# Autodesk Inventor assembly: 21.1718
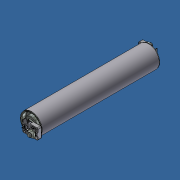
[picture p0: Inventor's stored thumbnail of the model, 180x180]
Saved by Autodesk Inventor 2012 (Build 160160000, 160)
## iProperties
Created: 2007-07
Part Number: 21.1718
Document SubType Name: Assembly
Designer: Andy Moles
Description: TRANSPORT ROLLER S AL
Author: Andy Moles
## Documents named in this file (4)
- Y:\INVENTOR LIBRARIES\PARTS LIBRARY\BELT AND ROLLER CONVEYORS\21.1718 TRANSPORT ROLLER S AL.iam
- Y:\INVENTOR LIBRARIES\PARTS LIBRARY\BELT AND ROLLER CONVEYORS\SUBCOMPONENTS\20.1041 TUBE AL 50X2 FOR 21.1718.IPT
- Y:\INVENTOR LIBRARIES\PARTS LIBRARY\BELT AND ROLLER CONVEYORS\21.1722 BEARING ASSEMBLY S.iam
- Y:\INVENTOR LIBRARIES\PARTS LIBRARY\BELT AND ROLLER CONVEYORS\SUBCOMPONENTS\17.1840 8mm STEEL ROD FOR TRANSPORT ROLLER.ipt
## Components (4 placed, 3 different names)
1. 20.1041 TUBE AL 50X2 FOR 21.1718:1 — Mate:1, Mate:2, Mate:3, Mate:5, Mate:6, Mate:7, Mate:8, Mate:9
2. 17.1840 8mm STEEL ROD FOR TRANSPORT ROLLER:1 — Mate:4, Mate:5
3. 21.1722 BEARING ASSEMBLY S:1 [sub-assembly] — Mate:6, Mate:7, Angle:1
4. 21.1722 BEARING ASSEMBLY S:2 [sub-assembly] — Mate:8, Mate:9, Angle:2
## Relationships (11: Mate 9, Angle 2)
- Mate:1: 20.1041 TUBE AL 50X2 FOR 21.1718:1
- Mate:2: 20.1041 TUBE AL 50X2 FOR 21.1718:1
- Mate:3: 20.1041 TUBE AL 50X2 FOR 21.1718:1
- Mate:4: 17.1840 8mm STEEL ROD FOR TRANSPORT ROLLER:1
- Mate:5: 20.1041 TUBE AL 50X2 FOR 21.1718:1 ↔ 17.1840 8mm STEEL ROD FOR TRANSPORT ROLLER:1
- Mate:6: 20.1041 TUBE AL 50X2 FOR 21.1718:1 ↔ 21.1722 BEARING ASSEMBLY S:1
- Mate:7: 20.1041 TUBE AL 50X2 FOR 21.1718:1 ↔ 21.1722 BEARING ASSEMBLY S:1
- Mate:8: 20.1041 TUBE AL 50X2 FOR 21.1718:1 ↔ 21.1722 BEARING ASSEMBLY S:2
- Mate:9: 20.1041 TUBE AL 50X2 FOR 21.1718:1 ↔ 21.1722 BEARING ASSEMBLY S:2
- Angle:1: 21.1722 BEARING ASSEMBLY S:1
- Angle:2: 21.1722 BEARING ASSEMBLY S:2
